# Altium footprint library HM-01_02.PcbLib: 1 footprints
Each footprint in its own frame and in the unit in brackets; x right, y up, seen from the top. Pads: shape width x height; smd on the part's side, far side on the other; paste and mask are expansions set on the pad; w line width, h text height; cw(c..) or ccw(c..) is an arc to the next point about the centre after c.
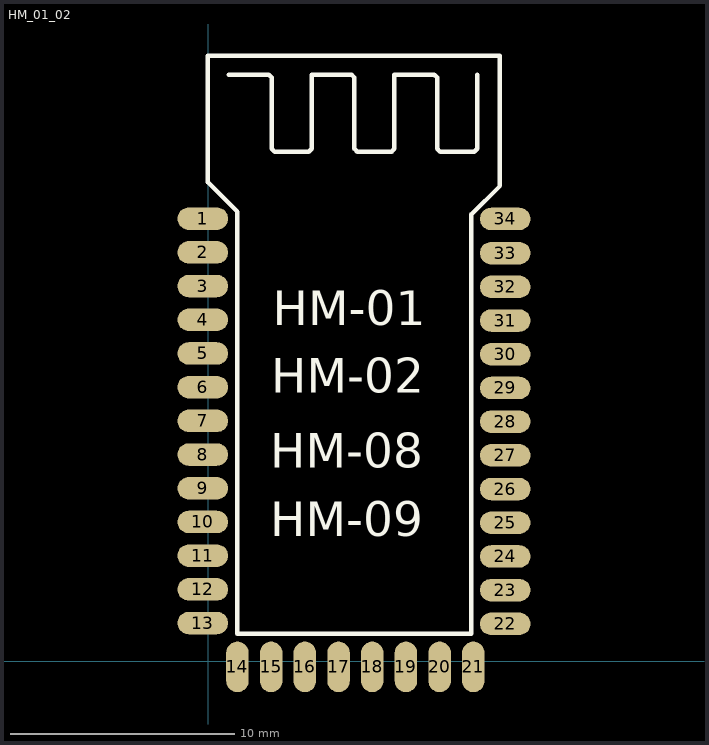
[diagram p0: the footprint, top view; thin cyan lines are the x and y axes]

## HM_01_02 [mil] "www.jnhuamao.cn"
pads (34):
  oval 88.74x39.37 smd: 1(-10,775.43) 2(-10,716.38) 3(-10,657.32) 4(-10,598.27) 5(-10,539.21) 6(-10,480.16) 7(-10,421.1) 8(-10,362.05) 9(-10,302.99) 10(-10,243.94) 11(-10,184.88) 12(-10,125.83) 13(-10,66.77) 22(520,65.43) 23(520,124.49) 24(520,183.54) 25(520,242.6) 26(520,301.65) 27(520,360.71) 28(520,419.76) 29(520,478.82) 30(520,537.87) 31(520,596.93) 32(520,655.98) 33(520,715.04) 34(520,775)
  oval 39.37x88.74 smd: 14(50.75,-10) 15(109.8,-10) 16(168.86,-10) 17(227.91,-10) 18(286.97,-10) 19(346.02,-10) 20(405.08,-10) 21(464.13,-10)
Top Overlay:
  lines w7.87: 35.75,1027.87 105.75,1027.87 110.75,1022.87 110.75,897.87 115.75,892.87 175.75,892.87 180.75,897.87 180.75,1027.87 250.75,1027.87 255.75,1022.87 255.75,897.87 260.75,892.87 320.75,892.87 325.75,897.87 325.75,1027.87 395.75,1027.87 400.75,1022.87 400.75,897.87 405.75,892.87 465.75,892.87 470.75,897.87 470.75,1027.87 ; -1.06,839.68 -1.06,1060.87 510.75,1060.87 510.75,832.87 460.75,782.87 460.75,47.87 50.75,47.87 50.75,787.87 -1.06,839.68
  text "HM-01" at 112.97,588.94 h60
  text "HM-02" at 110,470 h60
  text "HM-08" at 107.97,338.94 h60
  text "HM-09" at 107.97,218.94 h60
